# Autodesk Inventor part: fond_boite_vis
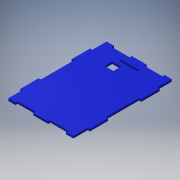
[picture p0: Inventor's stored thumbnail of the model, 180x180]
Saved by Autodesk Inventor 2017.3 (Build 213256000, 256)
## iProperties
Part Number: fond_boite_vis
Material: Générique
Document SubType Name: Modeling
Designer: ficho
Density: 1 g/cm^3
Appearance: Bleu - Peinture murale - Brillant
Author: ficho
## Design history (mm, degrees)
sketch "Esquisse1"
  geometry: L1 (96.09, 116.15)-(93.09, 116.15); L2 (93.09, 116.15)-(93.09, 136); L3 (93.09, 0)-(93.09, 19.85); L4 (93.09, 19.85)-(96, 19.85); L5 (96.09, 90.85)-(93, 90.85); L6 (93, 90.85)-(93, 45.15); L7 (93, 45.15)-(96, 45.15); L8 (96, 19.85)-(96, 45.15); L9 (96.09, 90.85)-(96.09, 116.15); L10 (0, 116.15)-(3, 116.15); L11 (3, 90.85)-(0, 90.85); L12 (0, 90.85)-(0, 116.15); L13 (0, 45.15)-(3, 45.15); L14 (3, 19.85)-(0, 19.85); L15 (0, 19.85)-(0, 45.15); L16 (3, 19.85)-(0, 19.85); L17 (3, 0)-(3, 19.85); L18 (3, 90.85)-(3, 45.15); L19 (3, 136)-(3, 116.15); L20 (3, 116.15)-(0, 116.15); L21 (0, 116.15)-(0, 90.85); L22 (0, 45.15)-(0, 19.85); L23 (37.7, 136)-(37.7, 133); L24 (37.7, 133)-(13, 133); L25 (13, 133)-(13, 136); L26 (58.39, 136)-(58.39, 133); L27 (58.39, 133)-(83.09, 133); L28 (83.09, 133)-(83.09, 136); L29 (13, 136)-(3, 136); L30 (93.09, 136)-(83.09, 136); L31 (58.39, 136)-(37.7, 136); L32 (37.7, 0)-(37.7, 3); L33 (37.7, 3)-(13, 3); L34 (13, 3)-(13, 0); L35 (83.09, 0)-(83.09, 3); L36 (83.09, 3)-(58.39, 3); L37 (58.39, 3)-(58.39, 0); L38 (83.09, 0)-(93.09, 0); L39 (3, 0)-(13, 0); L40 (37.7, 0)-(58.39, 0); 1 further point
  constraints: 80 end point, 20 parallel, 7 horizontal, 7 perpendicular, 3 point on line
  dimensions: "d2" = 3 distance of L1.start L1.end; "d6" = 25.3 distance between parallel lines of L5 L1; "d7" = 25.3 distance between parallel lines of L7 L4 (= d6); "d9" = 3 distance of L11.start L11.end; "d11" = 25.3 distance between parallel lines of L11 L10; "d14" = 25.3 distance between parallel lines of L13 L14 (= d7); "d15" = 24.7 distance of L23.end L24.end; "d16" = 24.7 distance of L27.end L26.end; "d17" = 10 distance between parallel lines of L25 L19; "d18" = 10 distance between parallel lines of L28 L2 (= d17); "d20" = 3 distance between parallel lines of L24 L31; "d21" = 3 distance between parallel lines of L27 L31 (derived); "d24" = 19.85 distance between parallel lines of L1 L30; "d25" = 19.85 distance between parallel lines of L10 L29; "d26" = 3 distance of L32.end L32.start; "d27" = 10 distance between parallel lines of L34 L17; "d28" = 24.7 distance between parallel lines of L32 L34; "d29" = 24.7 distance between parallel lines of L35 L37; "d30" = 10 distance between parallel lines of L3 L35
extrude "Extrusion1" new body sketch "Esquisse1" distance "d31" = 3; taper "d32" = 0 deg
sketch "Esquisse2"
  geometry: L1 (-42.418, 105.38)-(-31.298, 105.38) reference; L2 (-30.838, 105.94)-(-30.838, 115.59) reference; L3 (-30.838, 115.59)-(-30.838, 116) reference; L4 (-30.838, 116)-(-42.878, 116) reference; L5 (-42.878, 116)-(-42.878, 115.59) reference; L6 (-42.878, 115.59)-(-42.878, 105.94) reference; L7 (-42.878, 105.84)-(-42.878, 108.74) reference; L8 (-30.838, 108.74)-(-30.838, 105.84) reference; L9 (-30.338, 105.94)-(-30.338, 115.59); L10 (-30.338, 115.59)-(-30.338, 116.5); L11 (-30.338, 116.5)-(-43.378, 116.5); L12 (-43.378, 116.5)-(-43.378, 115.59); L13 (-43.378, 115.59)-(-43.378, 105.94); L14 (-43.378, 105.94)-(-43.378, 105.44); L15 (-42.878, 104.94)-(-30.838, 104.94); L16 (-30.338, 105.44)-(-30.338, 105.94); A1 r 0.5 centre (-30.838, 105.44) between (-30.838, 104.94) and (-30.338, 105.44); A2 r 0.5 centre (-42.878, 105.44) between (-43.378, 105.44) and (-42.878, 104.94); 1 further point
  constraints: 17 end point, 4 point on circle, 4 tangent, 2 centre point, 1 equal radius, 1 parallel, 4 other
  dimensions: "d33" = 0.5 distance between parallel lines of L2 L9; "d35" = 0.5 radius of A1
extrude "Extrusion2" cut sketch "Esquisse2" stored distance "d36" = 10; taper "d37" = 0 deg
sketch "Esquisse3"
  geometry: L1 (-60.65, 124.5)-(-35.35, 124.5); L2 (-35.35, 121.5)-(-60.65, 121.5); L3 (-31.298, 105.38)-(-42.418, 105.38) reference; L4 (-42.878, 105.84)-(-42.878, 116) reference; L5 (-42.878, 116)-(-30.838, 116) reference; L6 (-30.838, 116)-(-30.838, 105.84) reference; L7 (-96.09, 116.15)-(-96.09, 90.85) reference; L8 (-96.09, 90.85)-(-93, 90.85) reference; L9 (-93, 90.85)-(-93, 45.15) reference; L10 (-93, 45.15)-(-96, 45.15) reference; L11 (-96, 45.15)-(-96, 19.85) reference; L12 (-96, 19.85)-(-93.09, 19.85) reference; L13 (-93.09, 19.85)-(-93.09, 0) reference; L14 (-93.09, 0)-(-83.09, 0) reference; L15 (-83.09, 0)-(-83.09, 3) reference; L16 (-83.09, 3)-(-58.39, 3) reference; L17 (-58.39, 3)-(-58.39, 0) reference; L18 (-58.39, 0)-(-37.7, 0) reference; L19 (-37.7, 0)-(-37.7, 3) reference; L20 (-37.7, 3)-(-13, 3) reference; L21 (-13, 3)-(-13, 0) reference; L22 (-13, 0)-(-3, 0) reference; L23 (-3, 0)-(-3, 19.85) reference; L24 (-3, 19.85)-(0, 19.85) reference; L25 (0, 19.85)-(0, 45.15) reference; L26 (0, 45.15)-(-3, 45.15) reference; L27 (-3, 45.15)-(-3, 90.85) reference; L28 (-3, 90.85)-(0, 90.85) reference; L29 (0, 90.85)-(0, 116.15) reference; L30 (0, 116.15)-(-3, 116.15) reference; L31 (-3, 116.15)-(-3, 136) reference; L32 (-3, 136)-(-13, 136) reference; L33 (-13, 136)-(-13, 133) reference; L34 (-13, 133)-(-37.7, 133) reference; L35 (-37.7, 133)-(-37.7, 136) reference; L36 (-37.7, 136)-(-58.39, 136) reference; L37 (-58.39, 136)-(-58.39, 133) reference; L38 (-58.39, 133)-(-83.09, 133) reference; L39 (-83.09, 133)-(-83.09, 136) reference; L40 (-83.09, 136)-(-93.09, 136) reference; L41 (-93.09, 136)-(-93.09, 116.15) reference; L42 (-93.09, 116.15)-(-96.09, 116.15) reference; L43 (-35.65, 121.5)-(-35.65, 124.5); L44 (-60.35, 121.5)-(-60.35, 124.5); 1 further point
  constraints: 8 end point, 4 point on line, 2 other
extrude "Extrusion3" cut sketch "Esquisse3" stored distance "d40" = 10; taper "d41" = 0 deg
node "Solide1"
node "Référence1"
node "Référence2"
node "Référence3"
node "Référence4"
node "Référence5"
node "Référence6"
node "Référence7"
node "Référence8"
node "Référence9"
node "Référence10"
node "Boucle projetée1"
other parameters: "d1" = 136, "d3" = 19.85, "d4" = 19.85 (= d3), "d5" = 3 (derived), "d8" = 96, "d10" = 19.85, "d13" = 19.85 (= d4), "d19" = 136, "d22" = 136, "d23" = 136 (= d22)
